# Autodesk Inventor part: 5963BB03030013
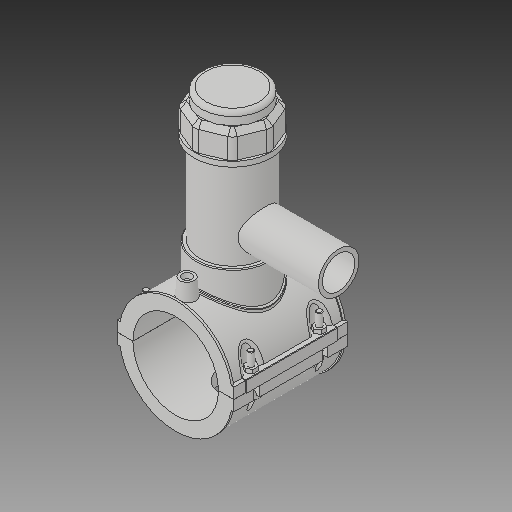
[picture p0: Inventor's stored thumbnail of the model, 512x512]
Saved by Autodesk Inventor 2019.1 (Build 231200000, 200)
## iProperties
Created: 2017-07
Part Number: 5963BB03030013
Material: Generic
Description: PLASSON TAPPING SADDLE 3''IPS x 1 1/4''IPS
Document SubType Name: Modeling
Designer: KIM
Mass: 1712.7 g
Surface Area: 2671.49 cm^2
Volume: 1712.7 cm^3
Density: 1 g/cm^3
Appearance: Default
Author: KIM
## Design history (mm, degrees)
derived "5963B.ipt"
feature "Solid1::5963B.ipt"
feature "Solid2::5963B.ipt"
feature "Solid4::5963B.ipt"
feature "Solid5::5963B.ipt"
tag "TaggingFeature1"
body "Solid1"
body "Solid2"
other parameters: "d0" = 88.7, "d2" = 120.904, "d3" = 22.175, "d4" = 118.11, "d5" = 0, "d6" = 0.1, "d8" = 0, "d19" = 6, "d20" = 6, "d21" = 70.866, "d23" = 0, "d24" = 35.433, "d26" = 0, "d29" = 3, "d30" = 29.56667, "d31" = 6, "d32" = 0, "d33" = 0, "d34" = 0.6, "d40" = 59.9612, "d41" = 79.83, "d43" = 0, "d45" = 0, "d47" = 128.521, "d70" = 15, "d72" = 0, "d73" = 6, "d75" = 5, "d76" = 0, "d77" = 4.435, "d78" = 74.35, "d79" = 15, "d80" = 47.244, "d82" = 5 deg, "d84" = 4, "d85" = 14, "d86" = 0, "d87" = 3, "d88" = 0, "d89" = 1, "d90" = 1, "d91" = 94.488, "d92" = 0, "d93" = 0.5, "d94" = 46.68421, "d96" = 117.6162, "d97" = 2.3622, "d98" = 0, "d102" = 0.887, "d120" = 140 deg, "d121" = 24.228, "d122" = 20 deg, "d123" = 230.62, "d124" = 69.186, "d126" = 0, "d143" = 91.361, "d145" = 20.46923, "d149" = 1.3305, "d150" = 22.51615, "d153" = 118.11, "d154" = 0, "d156" = 57.655, "d157" = 160 deg, "d159" = 5.322, "d161" = 1.3305, "d162" = 70.866, "d163" = 0, "d164" = 44.35, "d167" = 8.87, "d168" = 56.24878, "d170" = 3.2805, "d172" = 0, "d173" = 1, "d175" = 44.35, "d176" = 20 deg, "d177" = 6.209, "d178" = 26.61, "d180" = 0, "d183" = 10.644, "d184" = 4.9672, "d185" = 38.38575, "d186" = 38.38575, "d187" = 57.655, "d188" = 7.983, "d189" = 6.209, "d190" = 0, "d191" = 86.4825, "d193" = 6.1236, "d194" = 4.13385, "d195" = 90 deg, "d197" = 0, "d199" = 0, "d200" = 13.305, "d202" = 0, "d203" = 177.038, "d204" = 75.8385, "d205" = 55.881, "d206" = 67.8555, "d207" = 132.7785, "d208" = 138.08964, "d209" = 164.64534, "d210" = 68.6538, "d211" = 79.83, "d212" = 63.864, "d213" = 39.5766, "d216" = 0, "d217" = 8.87, "d218" = 4.435, "d219" = 0.887, "d222" = 88.7, "d224" = 0, "d230" = 5.322, "d233" = 6, "d236" = 60.452, "d237" = 35.433, "d238" = 6.02433, "d240" = 35.433, "d241" = 35.433, "d242" = 35.433, "d243" = 6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
